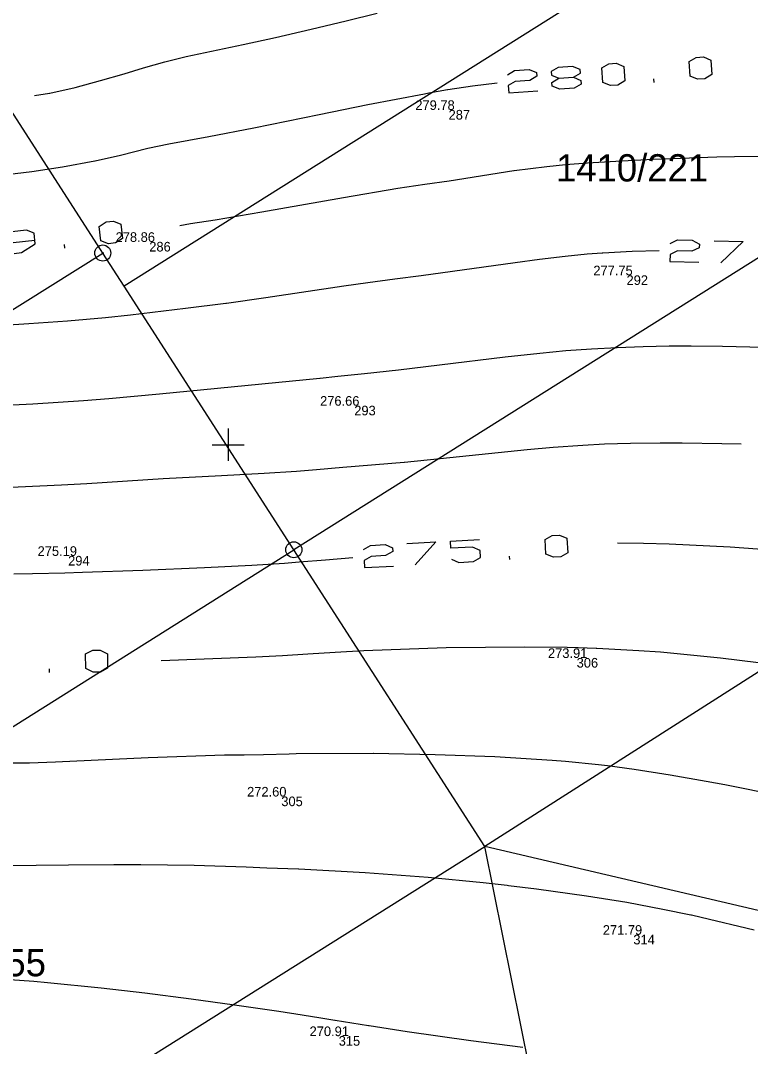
# Model space of a CAD drawing. Extents: x -771260 to -770828, y -1053564 to -1052811.
# Drawn here: x -771112.9 to -771067.4, y -1053187.5 to -1053123.6 of the extents above; entities that cross this region are included whole.
import ezdxf

# ---------------------------------------------------------------- set-up
doc = ezdxf.new("R2010")
doc.units = 0
for name, color, linetype in [('14_8_2023_krizky', 7, 'Continuous'), ('25_3_2019_krizky_JTSK', 7, 'Continuous'), ('25_3_2019_vrstevnice_interval_po_1m', 7, 'Continuous'), ('25_3_2019_zamereny_bod', 7, 'Continuous'), ('25_3_2019_zamereny_bod_cislo', 7, 'Continuous'), ('25_3_2019_zamereny_bod_vyska', 7, 'Continuous'), ('Default', 7, 'Continuous'), ('DKM_Hranice parcel', 7, 'Continuous'), ('DKM_Parcelní čísla', 7, 'Continuous'), ('DKM_Značky bodu BP', 7, 'Continuous')]:
    doc.layers.add(name, color=color, linetype=linetype)

# ---------------------------------------------------------------- blocks, each defined once
blk = doc.blocks.new('POINT_DISPLAY')
at = {"layer": 'Default'}
blk.add_line((0, 0), (0, 0), dxfattribs=at)
blk = doc.blocks.new('KRIZEK')
at = {"layer": '25_3_2019_krizky_JTSK'}
for p, q in [((0, 10), (0, -10)), ((-10, 0), (10, 0))]:
    blk.add_line(p, q, dxfattribs=at)

msp = doc.modelspace()

# ---------------------------------------------------------------- linework, layer by layer
at = {"layer": '25_3_2019_vrstevnice_interval_po_1m'}
for points in [[(-771112.062, -1053128.24), (-771111.132, -1053128.078), (-771111.115, -1053128.075), (-771109.537, -1053127.725), (-771107.943, -1053127.298), (-771106.484, -1053126.872), (-771105.271, -1053126.507), (-771103.937, -1053126.125), (-771102.615, -1053125.799), (-771102.614, -1053125.798), (-771099.061, -1053125.049), (-771097.045, -1053124.608), (-771094.82, -1053124.098), (-771092.644, -1053123.571), (-771090.707, -1053123.101)], [(-771094.82, -1053124.098), (-771094.82, -1053124.098)], [(-771097.045, -1053124.608), (-771097.045, -1053124.608)], [(-771099.061, -1053125.049), (-771099.061, -1053125.049)], [(-771102.614, -1053125.798), (-771102.614, -1053125.798)], [(-771070.727, -1053127.216), (-771071.196, -1053127.023), (-771071.261, -1053126.117), (-771070.825, -1053125.858), (-771070.372, -1053125.826), (-771069.903, -1053126.019), (-771069.838, -1053126.925), (-771070.274, -1053127.184), (-771070.727, -1053127.216)], [(-771105.271, -1053126.507), (-771105.271, -1053126.507)], [(-771103.937, -1053126.125), (-771103.937, -1053126.125)], [(-771082.578, -1053126.936), (-771082.142, -1053126.677), (-771081.237, -1053126.611), (-771080.768, -1053126.805), (-771080.751, -1053127.031), (-771081.188, -1053127.29), (-771082.093, -1053127.356), (-771082.529, -1053127.615), (-771082.496, -1053128.068), (-771080.686, -1053127.937)], [(-771078.471, -1053127.094), (-771078.035, -1053126.835), (-771078.051, -1053126.609), (-771078.521, -1053126.415), (-771079.426, -1053126.48), (-771079.862, -1053126.74), (-771079.846, -1053126.966), (-771079.377, -1053127.159)], [(-771076.159, -1053127.609), (-771076.628, -1053127.416), (-771076.693, -1053126.51), (-771076.257, -1053126.251), (-771075.804, -1053126.219), (-771075.335, -1053126.412), (-771075.27, -1053127.317), (-771075.706, -1053127.577), (-771076.159, -1053127.609)], [(-771107.943, -1053127.298), (-771107.943, -1053127.298)], [(-771106.484, -1053126.872), (-771106.484, -1053126.872)], [(-771078.471, -1053127.094), (-771078.002, -1053127.288), (-771077.986, -1053127.514), (-771078.422, -1053127.773), (-771079.328, -1053127.839), (-771079.797, -1053127.645), (-771079.813, -1053127.419), (-771079.377, -1053127.159)], [(-771079.377, -1053127.159), (-771078.471, -1053127.094)], [(-771073.443, -1053127.413), (-771073.459, -1053127.187)], [(-771113.789, -1053133.158), (-771112.242, -1053132.963), (-771110.317, -1053132.668), (-771108.303, -1053132.299), (-771108.286, -1053132.295), (-771106.712, -1053131.94), (-771105.01, -1053131.521), (-771103.697, -1053131.239), (-771103.696, -1053131.239), (-771101.195, -1053130.781), (-771098.39, -1053130.241), (-771094.324, -1053129.421), (-771091.295, -1053128.801), (-771087.754, -1053128.116), (-771087.475, -1053128.067), (-771086.313, -1053127.866), (-771086.307, -1053127.865), (-771084.767, -1053127.636), (-771083.225, -1053127.438)], [(-771109.537, -1053127.725), (-771109.537, -1053127.725)], [(-771086.307, -1053127.865), (-771086.307, -1053127.865)], [(-771084.767, -1053127.636), (-771084.767, -1053127.636)], [(-771112.062, -1053128.24), (-771112.062, -1053128.24)], [(-771111.115, -1053128.075), (-771111.115, -1053128.075)], [(-771087.754, -1053128.116), (-771087.754, -1053128.116)], [(-771091.295, -1053128.801), (-771091.295, -1053128.801)], [(-771094.324, -1053129.421), (-771094.324, -1053129.421)], [(-771098.39, -1053130.241), (-771098.39, -1053130.241)], [(-771101.195, -1053130.781), (-771101.195, -1053130.781)], [(-771105.01, -1053131.521), (-771105.01, -1053131.521)], [(-771103.696, -1053131.239), (-771103.696, -1053131.239)], [(-771108.286, -1053132.295), (-771108.286, -1053132.295)], [(-771106.712, -1053131.94), (-771106.712, -1053131.94)], [(-771103.005, -1053136.326), (-771102.336, -1053136.22), (-771100.815, -1053135.978), (-771097.902, -1053135.48), (-771092.805, -1053134.58), (-771089.417, -1053134.016), (-771087.732, -1053133.766), (-771086.225, -1053133.543), (-771082.184, -1053132.913), (-771082.16, -1053132.909), (-771080.122, -1053132.646), (-771078.961, -1053132.534), (-771077.59, -1053132.423), (-771075.832, -1053132.319), (-771073.506, -1053132.209), (-771071.806, -1053132.129), (-771069.523, -1053132.051), (-771068.42, -1053132.026), (-771065.967, -1053132.003)], [(-771077.59, -1053132.423), (-771077.59, -1053132.423)], [(-771075.832, -1053132.319), (-771075.832, -1053132.319)], [(-771071.806, -1053132.129), (-771071.806, -1053132.129)], [(-771069.523, -1053132.051), (-771069.523, -1053132.051)], [(-771068.42, -1053132.026), (-771068.42, -1053132.026)], [(-771112.242, -1053132.963), (-771112.242, -1053132.963)], [(-771110.317, -1053132.668), (-771110.317, -1053132.668)], [(-771082.16, -1053132.909), (-771082.16, -1053132.909)], [(-771080.122, -1053132.646), (-771080.122, -1053132.646)], [(-771078.961, -1053132.534), (-771078.961, -1053132.534)], [(-771086.225, -1053133.543), (-771086.225, -1053133.543)], [(-771089.417, -1053134.016), (-771089.417, -1053134.016)], [(-771092.805, -1053134.58), (-771092.805, -1053134.58)], [(-771097.902, -1053135.48), (-771097.902, -1053135.48)], [(-771107.463, -1053137.469), (-771107.938, -1053137.29), (-771108.031, -1053136.387), (-771107.602, -1053136.115), (-771107.151, -1053136.068), (-771106.676, -1053136.248), (-771106.583, -1053137.151), (-771107.011, -1053137.423), (-771107.463, -1053137.469)], [(-771100.815, -1053135.978), (-771100.815, -1053135.978)], [(-771113.332, -1053138.073), (-771112.881, -1053138.027), (-771112.024, -1053137.482), (-771112.094, -1053136.805), (-771112.569, -1053136.626), (-771113.472, -1053136.719), (-771113.9, -1053136.991), (-771113.877, -1053137.217), (-771113.402, -1053137.396), (-771112.047, -1053137.256)], [(-771103.005, -1053136.326), (-771103.005, -1053136.326)], [(-771110.172, -1053137.748), (-771110.195, -1053137.522)], [(-771072.432, -1053137.452), (-771071.973, -1053137.236), (-771071.066, -1053137.258), (-771070.617, -1053137.495), (-771070.623, -1053137.722), (-771071.082, -1053137.938), (-771071.989, -1053137.916), (-771072.449, -1053138.132), (-771072.46, -1053138.586), (-771070.645, -1053138.63)], [(-771069.704, -1053137.29), (-771067.89, -1053137.334), (-771069.283, -1053138.662)], [(-771114.009, -1053142.541), (-771112.419, -1053142.445), (-771110.015, -1053142.269), (-771107.645, -1053142.062), (-771106.087, -1053141.898), (-771102.658, -1053141.495), (-771100.135, -1053141.175), (-771100.108, -1053141.171), (-771097.649, -1053140.823), (-771092.774, -1053140.091), (-771091.287, -1053139.878), (-771089.614, -1053139.667), (-771087.972, -1053139.459), (-771082.097, -1053138.637), (-771080.596, -1053138.44), (-771078.984, -1053138.25), (-771077.614, -1053138.111), (-771076.671, -1053138.036), (-771076.645, -1053138.034), (-771074.817, -1053137.942), (-771073.124, -1053137.889)], [(-771077.614, -1053138.111), (-771077.614, -1053138.111)], [(-771076.645, -1053138.034), (-771076.645, -1053138.034)], [(-771074.817, -1053137.942), (-771074.817, -1053137.942)], [(-771074.817, -1053137.942), (-771074.817, -1053137.942)], [(-771082.097, -1053138.637), (-771082.097, -1053138.637)], [(-771080.596, -1053138.44), (-771080.596, -1053138.44)], [(-771078.984, -1053138.25), (-771078.984, -1053138.25)], [(-771087.972, -1053139.459), (-771087.972, -1053139.459)], [(-771092.774, -1053140.091), (-771092.774, -1053140.091)], [(-771091.287, -1053139.878), (-771091.287, -1053139.878)], [(-771100.108, -1053141.171), (-771100.108, -1053141.171)], [(-771097.649, -1053140.823), (-771097.649, -1053140.823)], [(-771106.087, -1053141.898), (-771106.087, -1053141.898)], [(-771106.087, -1053141.898), (-771106.087, -1053141.898)], [(-771102.658, -1053141.495), (-771102.658, -1053141.495)], [(-771112.419, -1053142.445), (-771112.419, -1053142.445)], [(-771110.015, -1053142.269), (-771110.015, -1053142.269)], [(-771107.645, -1053142.062), (-771107.645, -1053142.062)], [(-771114.72, -1053147.582), (-771112.174, -1053147.448), (-771109.019, -1053147.243), (-771107.435, -1053147.115), (-771107.434, -1053147.115), (-771104.276, -1053146.822), (-771094.283, -1053145.852), (-771094.254, -1053145.85), (-771093.152, -1053145.727), (-771091.492, -1053145.555), (-771089.367, -1053145.335), (-771086.82, -1053145.025), (-771082.723, -1053144.526), (-771080.564, -1053144.286), (-771078.953, -1053144.137), (-771077.346, -1053144.017), (-771075.745, -1053143.93), (-771075.743, -1053143.93), (-771074.123, -1053143.87), (-771072.507, -1053143.838), (-771071.146, -1053143.832), (-771071.122, -1053143.832), (-771069.174, -1053143.858), (-771067.472, -1053143.903), (-771065.656, -1053143.968)], [(-771075.743, -1053143.93), (-771075.743, -1053143.93)], [(-771074.123, -1053143.87), (-771074.123, -1053143.87)], [(-771072.507, -1053143.838), (-771072.507, -1053143.838)], [(-771071.122, -1053143.832), (-771071.122, -1053143.832)], [(-771069.174, -1053143.858), (-771069.174, -1053143.858)], [(-771067.472, -1053143.903), (-771067.472, -1053143.903)], [(-771082.723, -1053144.526), (-771082.723, -1053144.526)], [(-771080.564, -1053144.286), (-771080.564, -1053144.286)], [(-771078.953, -1053144.137), (-771078.953, -1053144.137)], [(-771077.346, -1053144.017), (-771077.346, -1053144.017)], [(-771094.254, -1053145.85), (-771094.254, -1053145.85)], [(-771093.152, -1053145.727), (-771093.152, -1053145.727)], [(-771089.367, -1053145.335), (-771089.367, -1053145.335)], [(-771107.435, -1053147.115), (-771107.435, -1053147.115)], [(-771104.276, -1053146.822), (-771104.276, -1053146.822)], [(-771112.174, -1053147.448), (-771112.174, -1053147.448)], [(-771109.019, -1053147.243), (-771109.019, -1053147.243)], [(-771114.463, -1053152.688), (-771110.377, -1053152.498), (-771108.803, -1053152.411), (-771104.041, -1053152.108), (-771100.407, -1053151.912), (-771097.743, -1053151.768), (-771095.738, -1053151.641), (-771094.484, -1053151.548), (-771092.851, -1053151.41), (-771089.032, -1053151.088), (-771089.01, -1053151.086), (-771086.788, -1053150.869), (-771081.347, -1053150.293), (-771079.737, -1053150.149), (-771077.879, -1053150.02), (-771076.53, -1053149.951), (-771076.528, -1053149.95), (-771074.909, -1053149.899), (-771073.072, -1053149.876), (-771071.682, -1053149.878), (-771069.214, -1053149.915), (-771068.02, -1053149.952)], [(-771081.347, -1053150.293), (-771081.347, -1053150.293)], [(-771079.737, -1053150.149), (-771079.737, -1053150.149)], [(-771077.879, -1053150.02), (-771077.879, -1053150.02)], [(-771076.528, -1053149.95), (-771076.528, -1053149.95)], [(-771074.909, -1053149.899), (-771074.909, -1053149.899)], [(-771073.072, -1053149.876), (-771073.072, -1053149.876)], [(-771071.682, -1053149.878), (-771071.682, -1053149.878)], [(-771069.214, -1053149.915), (-771069.214, -1053149.915)], [(-771086.788, -1053150.869), (-771086.788, -1053150.869)], [(-771094.484, -1053151.548), (-771094.484, -1053151.548)], [(-771089.01, -1053151.086), (-771089.01, -1053151.086)], [(-771104.041, -1053152.108), (-771104.041, -1053152.108)], [(-771097.743, -1053151.768), (-771097.743, -1053151.768)], [(-771095.738, -1053151.641), (-771095.738, -1053151.641)], [(-771110.377, -1053152.498), (-771110.377, -1053152.498)], [(-771108.803, -1053152.411), (-771108.803, -1053152.411)], [(-771108.803, -1053152.411), (-771108.803, -1053152.411)], [(-771088.856, -1053156.156), (-771087.043, -1053156.056), (-771088.328, -1053157.49)], [(-771086.075, -1053157.139), (-771085.609, -1053157.341), (-771084.703, -1053157.291), (-771084.262, -1053157.039), (-771084.287, -1053156.586), (-771084.753, -1053156.385), (-771086.112, -1053156.459), (-771086.137, -1053156.006), (-771084.324, -1053155.906)], [(-771079.718, -1053157.016), (-771080.183, -1053156.815), (-771080.233, -1053155.908), (-771079.793, -1053155.657), (-771079.339, -1053155.632), (-771078.874, -1053155.834), (-771078.824, -1053156.74), (-771079.265, -1053156.991), (-771079.718, -1053157.016)], [(-771091.563, -1053156.532), (-771091.122, -1053156.281), (-771090.216, -1053156.231), (-771089.75, -1053156.432), (-771089.738, -1053156.659), (-771090.178, -1053156.911), (-771091.085, -1053156.96), (-771091.525, -1053157.212), (-771091.5, -1053157.665), (-771089.688, -1053157.565)], [(-771075.72, -1053156.115), (-771075.72, -1053156.115)], [(-771075.72, -1053156.115), (-771074.11, -1053156.135), (-771072.504, -1053156.179), (-771068.71, -1053156.369), (-771064.74, -1053156.662)], [(-771074.11, -1053156.135), (-771074.11, -1053156.135)], [(-771072.504, -1053156.179), (-771072.504, -1053156.179)], [(-771068.71, -1053156.369), (-771068.71, -1053156.369)], [(-771113.36, -1053158.04), (-771112.188, -1053158.021), (-771110.168, -1053157.989), (-771110.167, -1053157.989), (-771109.07, -1053157.949), (-771105.308, -1053157.812), (-771101.47, -1053157.652), (-771098.529, -1053157.501), (-771096.49, -1053157.375), (-771095.56, -1053157.309), (-771093.926, -1053157.169), (-771092.218, -1053157.023)], [(-771096.49, -1053157.375), (-771096.49, -1053157.375)], [(-771095.56, -1053157.309), (-771095.56, -1053157.309)], [(-771082.437, -1053157.166), (-771082.449, -1053156.94)], [(-771110.167, -1053157.989), (-771110.167, -1053157.989)], [(-771105.308, -1053157.812), (-771105.308, -1053157.812)], [(-771101.47, -1053157.652), (-771101.47, -1053157.652)], [(-771098.529, -1053157.501), (-771098.529, -1053157.501)], [(-771108.413, -1053164.176), (-771108.869, -1053163.954), (-771108.878, -1053163.046), (-771108.427, -1053162.815), (-771107.973, -1053162.81), (-771107.517, -1053163.033), (-771107.508, -1053163.94), (-771107.959, -1053164.172), (-771108.413, -1053164.176)], [(-771104.17, -1053163.454), (-771098.274, -1053163.231), (-771096.606, -1053163.144), (-771095.022, -1053163.041), (-771093.321, -1053162.932), (-771091.535, -1053162.831), (-771086.411, -1053162.649), (-771081.497, -1053162.591), (-771078.855, -1053162.631), (-771078.185, -1053162.642), (-771078.183, -1053162.642), (-771077.044, -1053162.677), (-771077.009, -1053162.679), (-771074.388, -1053162.829), (-771073.051, -1053162.918), (-771069.305, -1053163.281), (-771065.74, -1053163.731)], [(-771093.321, -1053162.932), (-771093.321, -1053162.932)], [(-771091.535, -1053162.831), (-771091.535, -1053162.831)], [(-771086.411, -1053162.649), (-771086.411, -1053162.649)], [(-771081.497, -1053162.591), (-771081.497, -1053162.591)], [(-771078.183, -1053162.642), (-771078.183, -1053162.642)], [(-771077.044, -1053162.677), (-771077.044, -1053162.677)], [(-771074.388, -1053162.829), (-771074.388, -1053162.829)], [(-771073.051, -1053162.918), (-771073.051, -1053162.918)], [(-771104.17, -1053163.454), (-771104.17, -1053163.454)], [(-771098.274, -1053163.231), (-771098.274, -1053163.231)], [(-771096.606, -1053163.144), (-771096.606, -1053163.144)], [(-771069.305, -1053163.281), (-771069.305, -1053163.281)], [(-771111.136, -1053164.203), (-771111.139, -1053163.976)], [(-771113.992, -1053169.842), (-771112.376, -1053169.828), (-771112.375, -1053169.828), (-771110.754, -1053169.763), (-771104.974, -1053169.496), (-771100.224, -1053169.342), (-771098.993, -1053169.326), (-771097.8, -1053169.31), (-771096.184, -1053169.268), (-771095.754, -1053169.256), (-771090.965, -1053169.233), (-771090.926, -1053169.233), (-771087.089, -1053169.305), (-771083.361, -1053169.448), (-771079.797, -1053169.667), (-771078.96, -1053169.737), (-771076.911, -1053169.933), (-771076.901, -1053169.933), (-771076.339, -1053170.001), (-771074.675, -1053170.226), (-771072.439, -1053170.571), (-771070.191, -1053170.972), (-771069.029, -1053171.187), (-771065.631, -1053171.868)], [(-771104.974, -1053169.496), (-771104.974, -1053169.496)], [(-771100.224, -1053169.342), (-771100.224, -1053169.342)], [(-771097.8, -1053169.31), (-771097.8, -1053169.31)], [(-771095.754, -1053169.256), (-771095.754, -1053169.256)], [(-771090.965, -1053169.233), (-771090.965, -1053169.233)], [(-771087.089, -1053169.305), (-771087.089, -1053169.305)], [(-771083.361, -1053169.448), (-771083.361, -1053169.448)], [(-771112.375, -1053169.828), (-771112.375, -1053169.828)], [(-771110.754, -1053169.763), (-771110.754, -1053169.763)], [(-771079.797, -1053169.667), (-771079.797, -1053169.667)], [(-771078.96, -1053169.737), (-771078.96, -1053169.737)], [(-771076.901, -1053169.933), (-771076.901, -1053169.933)], [(-771076.339, -1053170.001), (-771076.339, -1053170.001)], [(-771074.675, -1053170.226), (-771074.675, -1053170.226)], [(-771072.439, -1053170.571), (-771072.439, -1053170.571)], [(-771070.191, -1053170.972), (-771070.191, -1053170.972)], [(-771069.029, -1053171.187), (-771069.029, -1053171.187)], [(-771113.568, -1053176.225), (-771111.958, -1053176.219), (-771109.946, -1053176.185), (-771107.125, -1053176.179), (-771105.472, -1053176.165), (-771105.434, -1053176.165), (-771102.117, -1053176.209), (-771098.874, -1053176.308), (-771097.582, -1053176.369), (-771095.601, -1053176.448), (-771095.59, -1053176.448), (-771091.458, -1053176.668), (-771087.516, -1053176.958), (-771084.106, -1053177.289), (-771082.605, -1053177.463), (-771082.52, -1053177.473), (-771080.765, -1053177.688), (-771077.661, -1053178.123), (-771075.151, -1053178.527), (-771075.141, -1053178.528), (-771072.889, -1053178.949), (-771071.154, -1053179.304), (-771071.119, -1053179.312), (-771070.512, -1053179.447), (-771067.201, -1053180.24)], [(-771111.958, -1053176.219), (-771111.958, -1053176.219)], [(-771109.946, -1053176.185), (-771109.946, -1053176.185)], [(-771107.125, -1053176.179), (-771107.125, -1053176.179)], [(-771105.472, -1053176.165), (-771105.472, -1053176.165)], [(-771102.117, -1053176.209), (-771102.117, -1053176.209)], [(-771098.874, -1053176.308), (-771098.874, -1053176.308)], [(-771097.582, -1053176.369), (-771097.582, -1053176.369)], [(-771095.59, -1053176.448), (-771095.59, -1053176.448)], [(-771091.458, -1053176.668), (-771091.458, -1053176.668)], [(-771087.516, -1053176.958), (-771087.516, -1053176.958)], [(-771084.106, -1053177.289), (-771084.106, -1053177.289)], [(-771082.52, -1053177.473), (-771082.52, -1053177.473)], [(-771080.765, -1053177.688), (-771080.765, -1053177.688)], [(-771077.661, -1053178.123), (-771077.661, -1053178.123)], [(-771075.141, -1053178.528), (-771075.141, -1053178.528)], [(-771072.889, -1053178.949), (-771072.889, -1053178.949)], [(-771071.154, -1053179.304), (-771071.154, -1053179.304)], [(-771070.512, -1053179.447), (-771070.512, -1053179.447)], [(-771114.218, -1053183.298), (-771112.116, -1053183.45), (-771111.254, -1053183.52), (-771107.907, -1053183.854), (-771105.189, -1053184.165), (-771102.298, -1053184.536), (-771099.604, -1053184.916), (-771099.459, -1053184.937), (-771096.837, -1053185.322), (-771095.382, -1053185.553), (-771094.225, -1053185.726), (-771093.343, -1053185.873), (-771093.332, -1053185.875), (-771091.239, -1053186.208), (-771091.2, -1053186.214), (-771088.84, -1053186.577), (-771084.873, -1053187.134), (-771081.634, -1053187.555)], [(-771112.116, -1053183.45), (-771112.116, -1053183.45)], [(-771111.254, -1053183.52), (-771111.254, -1053183.52)], [(-771107.907, -1053183.854), (-771107.907, -1053183.854)], [(-771105.189, -1053184.165), (-771105.189, -1053184.165)], [(-771102.298, -1053184.536), (-771102.298, -1053184.536)], [(-771099.459, -1053184.937), (-771099.459, -1053184.937)], [(-771096.837, -1053185.322), (-771096.837, -1053185.322)], [(-771095.382, -1053185.553), (-771095.382, -1053185.553)], [(-771094.225, -1053185.726), (-771094.225, -1053185.726)], [(-771093.332, -1053185.875), (-771093.332, -1053185.875)], [(-771091.239, -1053186.208), (-771091.239, -1053186.208)], [(-771088.84, -1053186.577), (-771088.84, -1053186.577)], [(-771084.873, -1053187.134), (-771084.873, -1053187.134)]]:
    msp.add_lwpolyline(points, dxfattribs=at)
at = {"layer": 'DKM_Hranice parcel'}
for p, q in [((-771054.91, -1053107.7), (-771106.48, -1053140.11)), ((-771044.12, -1053124.01), (-771095.9, -1053156.55)), ((-771138.1, -1053157.08), (-771107.81, -1053138.05)), ((-771106.48, -1053140.11), (-771107.81, -1053138.05)), ((-771095.9, -1053156.55), (-771106.48, -1053140.11)), ((-771032.21, -1053142.02), (-771084, -1053175.04)), ((-771147.01, -1053188.66), (-771095.9, -1053156.55)), ((-771084, -1053175.04), (-771095.9, -1053156.55)), ((-771135.3, -1053207.29), (-771084, -1053175.04)), ((-771079.37, -1053198.03), (-771084, -1053175.04)), ((-771034.59, -1053186.63), (-771084, -1053175.04))]:
    msp.add_line(p, q, dxfattribs=at)
msp.add_lwpolyline([(-771107.81, -1053138.05), (-771117.05, -1053123.71), (-771080.25, -1053100.58)], dxfattribs=at)
at = {"layer": 'DKM_Značky bodu BP'}
for centre, radius in [((-771107.81, -1053138.05), 0.5), ((-771107.81, -1053138.05), 0.0303), ((-771095.9, -1053156.55), 0.5), ((-771095.9, -1053156.55), 0.0303)]:
    msp.add_circle(centre, radius, dxfattribs=at)

# ---------------------------------------------------------------- block references
at = {"layer": '14_8_2023_krizky', "xscale": 0.1, "yscale": 0.10000000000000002}
msp.add_blockref('KRIZEK', (-771100, -1053150), dxfattribs=at)
at = {"layer": '25_3_2019_zamereny_bod', "xscale": 0.1, "yscale": 0.10000000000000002}
for p in [(-771086.254, -1053129.13), (-771104.913, -1053137.356), (-771075.16, -1053139.44), (-771092.134, -1053147.57), (-771109.971, -1053156.932), (-771078.27, -1053163.295), (-771096.682, -1053171.934), (-771074.736, -1053180.553), (-771093.104, -1053186.869)]:
    msp.add_blockref('POINT_DISPLAY', p, dxfattribs=at)

# ---------------------------------------------------------------- texts
at = {"layer": '25_3_2019_zamereny_bod_cislo'}
for s, p in [('287', (-771086.254, -1053129.73)), ('286', (-771104.913, -1053137.956)), ('292', (-771075.16, -1053140.04)), ('293', (-771092.134, -1053148.17)), ('294', (-771109.971, -1053157.532)), ('306', (-771078.27, -1053163.895)), ('305', (-771096.682, -1053172.534)), ('314', (-771074.736, -1053181.153)), ('315', (-771093.104, -1053187.469))]:
    msp.add_text(s, height=0.6, dxfattribs=at).set_placement(p)
at = {"layer": '25_3_2019_zamereny_bod_vyska'}
for s, p in [('279.78 ', (-771088.326, -1053129.13)), ('278.86 ', (-771107.011, -1053137.356)), ('277.75 ', (-771077.23, -1053139.44)), ('276.66 ', (-771094.264, -1053147.57)), ('275.19 ', (-771111.874, -1053156.932)), ('273.91 ', (-771080.058, -1053163.295)), ('272.60 ', (-771098.814, -1053171.934)), ('271.79 ', (-771076.639, -1053180.553)), ('270.91 ', (-771094.918, -1053186.869))]:
    msp.add_text(s, height=0.6, dxfattribs=at).set_placement(p)
at = {"layer": 'DKM_Parcelní čísla'}
for s, p in [('1410/221', (-771079.555, -1053133.59)), ('1410/55', (-771119.57, -1053183.14))]:
    msp.add_text(s, height=1.7, dxfattribs=at).set_placement(p)

doc.saveas('drawing.dxf')
